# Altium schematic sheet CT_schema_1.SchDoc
size 568 x 258 mm
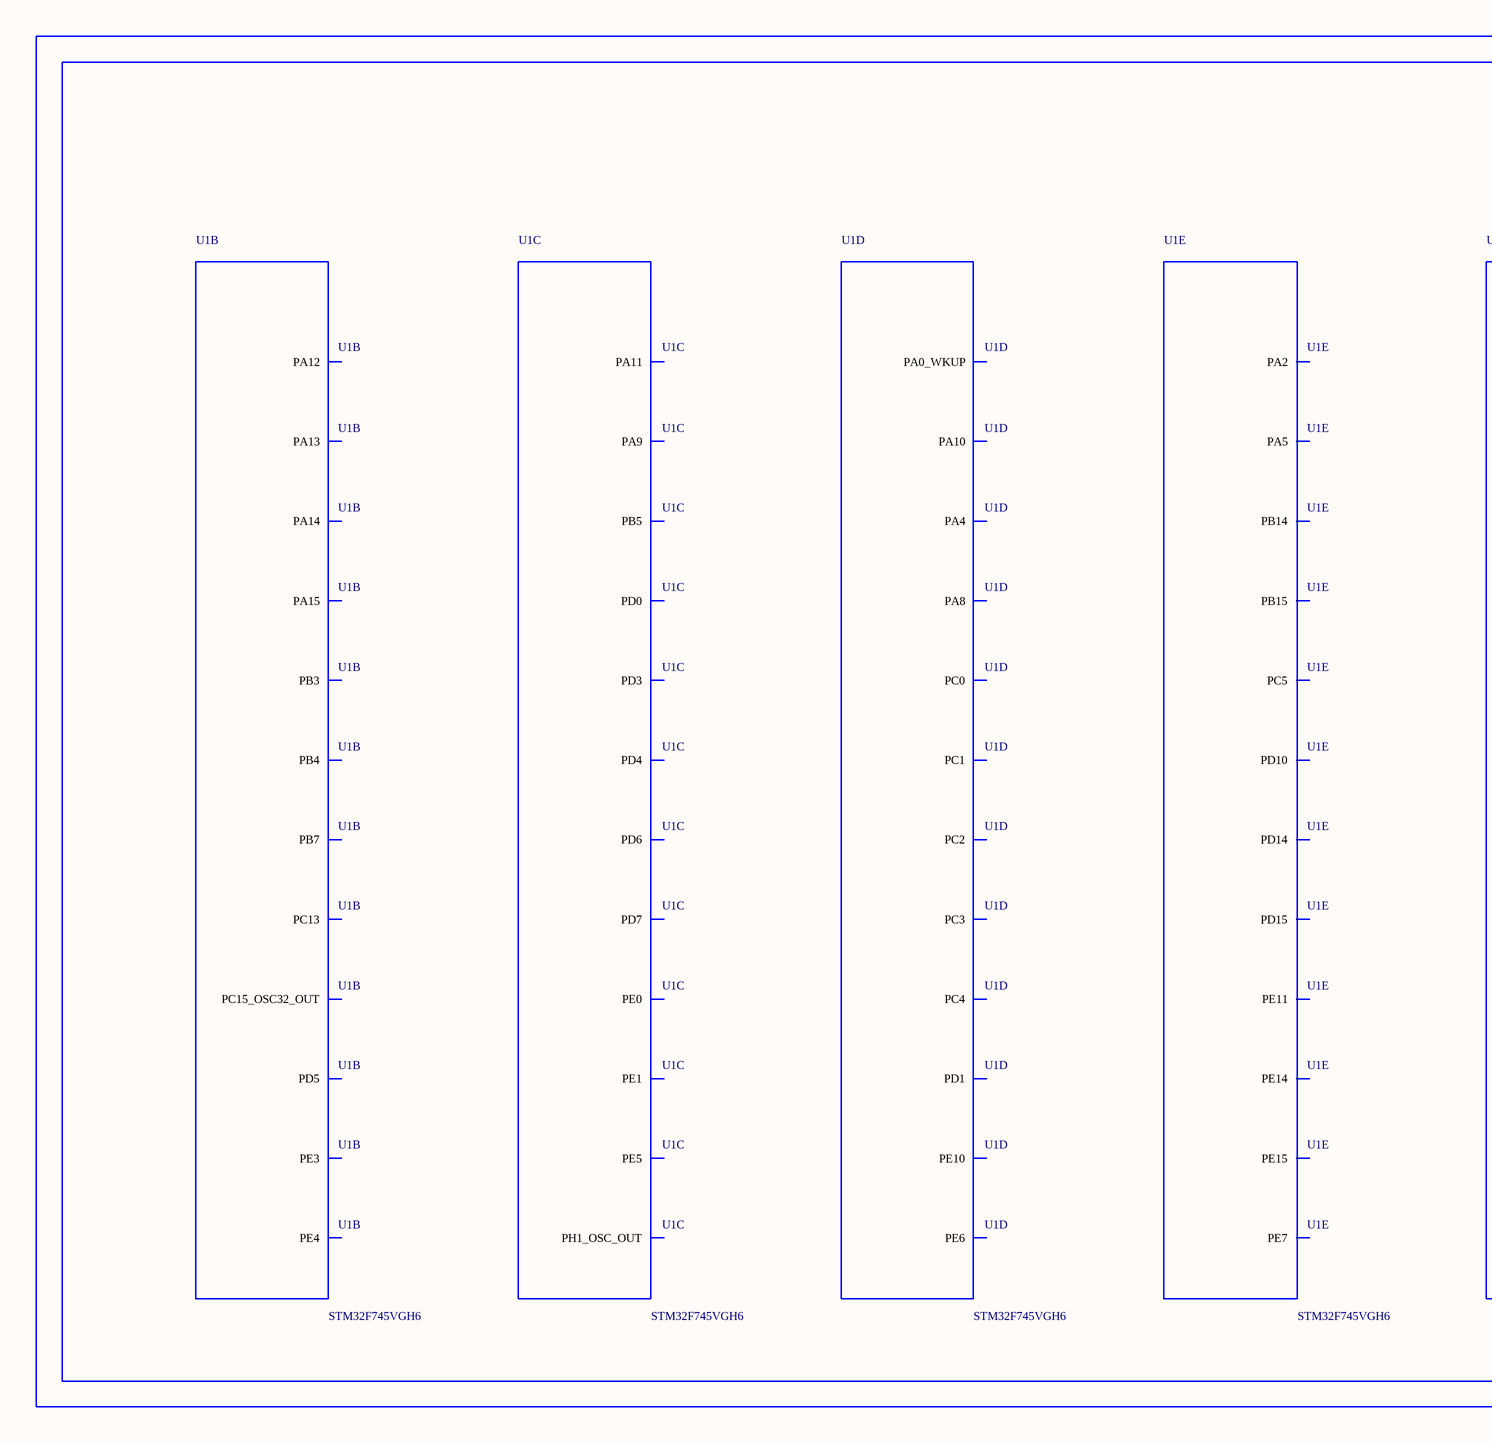
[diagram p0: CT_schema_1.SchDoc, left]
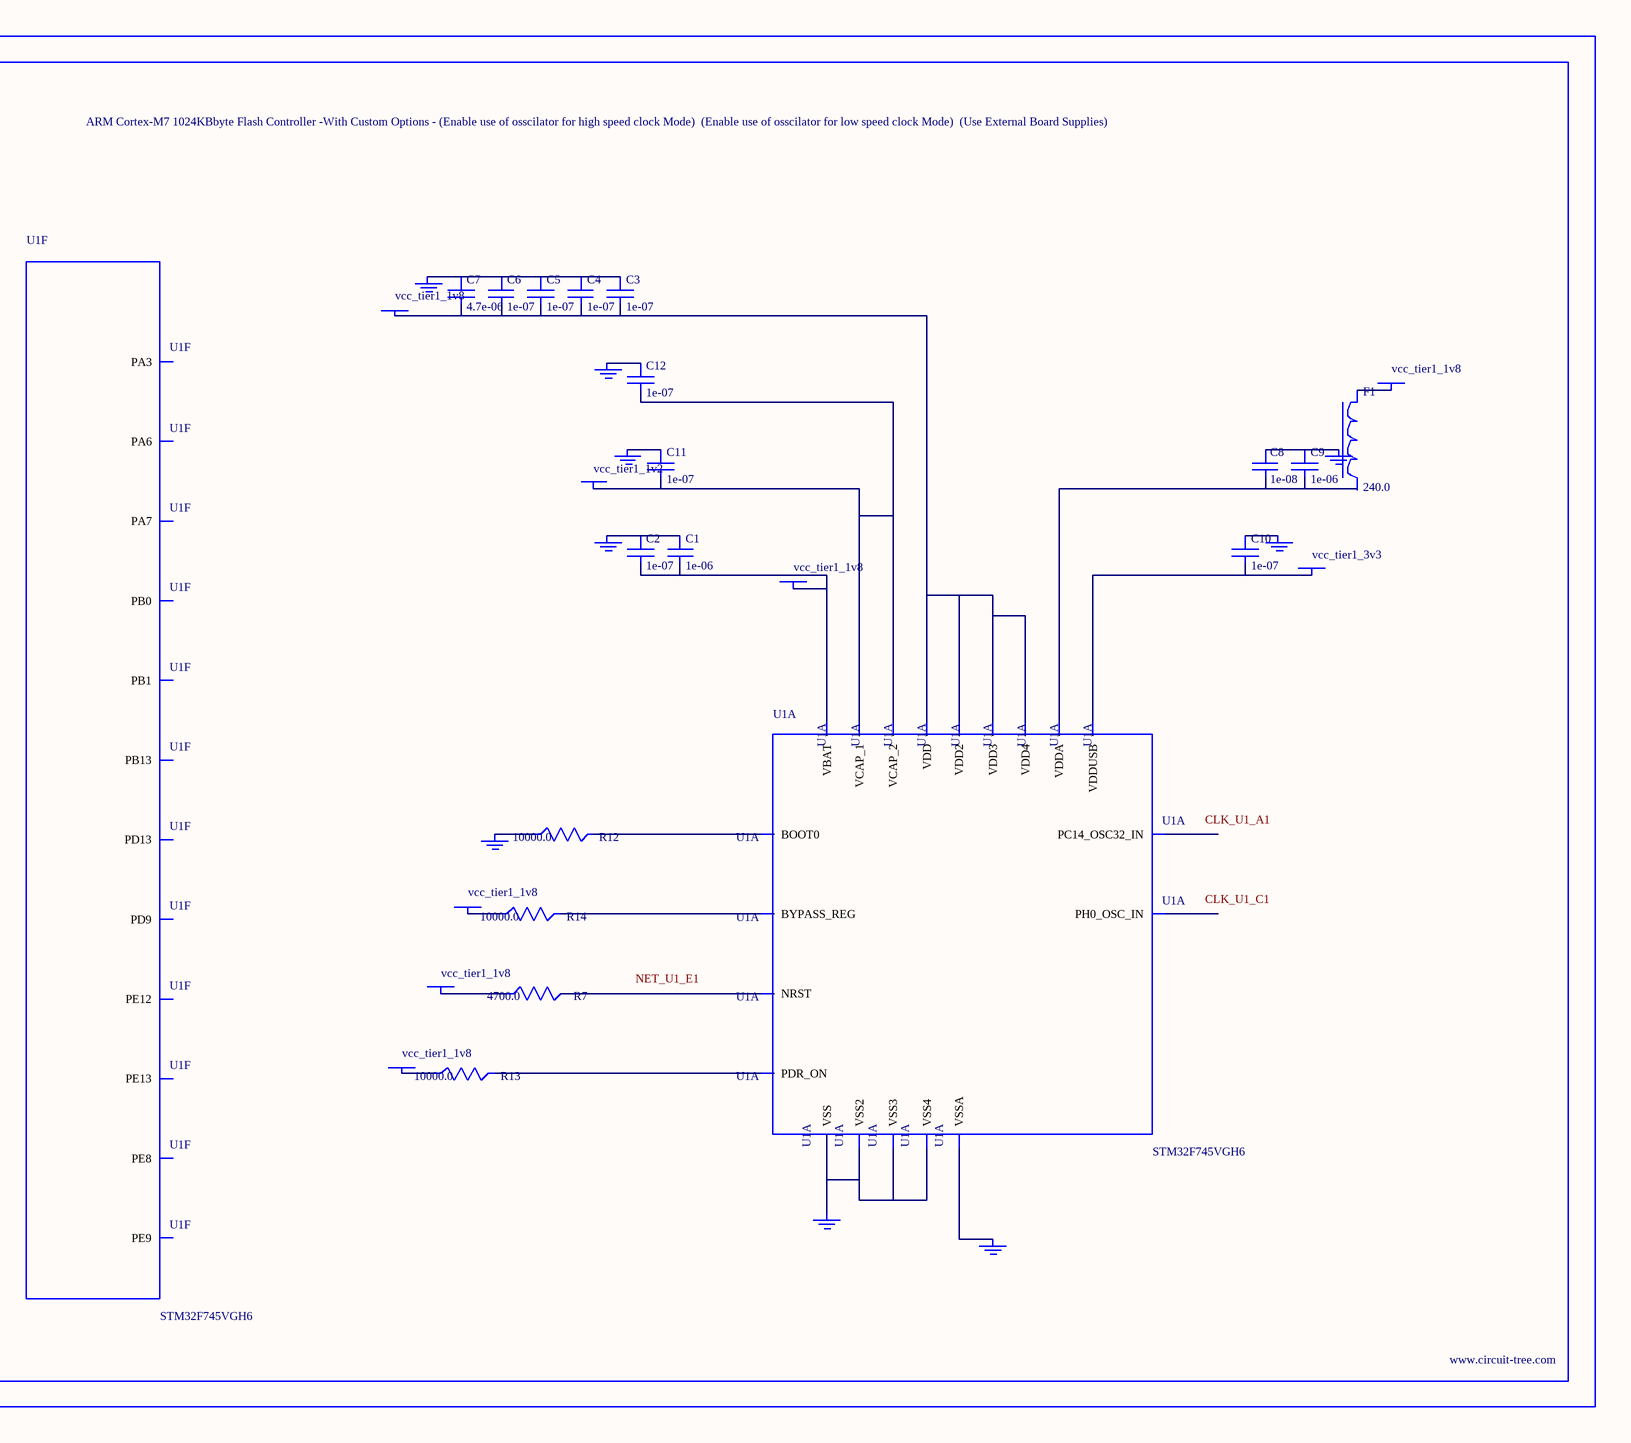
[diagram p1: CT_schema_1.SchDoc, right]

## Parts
BORDER0  (no value)
C1  1e-06  [C0603]
C2  1e-07  [C0603]
C3  1e-07  [C0603]
C4  1e-07  [C0603]
C5  1e-07  [C0603]
C6  1e-07  [C0603]
C7  4.7e-06  [C0603]
C8  1e-08  [C0603]
C9  1e-06  [C0603]
C10  1e-07  [C0603]
C11  1e-07  [C0603]
C12  1e-07  [C0603]
F1  240.0  [L0603]
GND_INSTANCE_0_0  (no value)
GND_INSTANCE_0_1  (no value)
GND_INSTANCE_0_2  (no value)
GND_INSTANCE_0_3  (no value)
GND_INSTANCE_0_4  (no value)
GND_INSTANCE_0_5  (no value)
GND_INSTANCE_0_6  (no value)
GND_INSTANCE_0_7  (no value)
GND_INSTANCE_0_8  (no value)
POWER_INSTANCE_0_0  vcc_tier1_1v8
POWER_INSTANCE_0_1  vcc_tier1_1v8
POWER_INSTANCE_0_2  vcc_tier1_1v8
POWER_INSTANCE_0_3  vcc_tier1_1v8
POWER_INSTANCE_0_4  vcc_tier1_3v3
POWER_INSTANCE_0_5  vcc_tier1_1v8
POWER_INSTANCE_0_6  vcc_tier1_1v2
POWER_INSTANCE_0_7  vcc_tier1_1v8
R7  4700.0  [R0603]
R12  10000.0  [R0603]
R13  10000.0  [R0603]
R14  10000.0  [R0603]
U1  STM32F745VGH6  [TFBGA100]  (parts A,B,C,D,E,F of 9)

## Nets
NetC1_1: C1.1 C2.1 GND_INSTANCE_0_0.0(GND)
NetC1_2: C1.2 C2.2 POWER_INSTANCE_0_0.0(PWR) U1.B2(VBAT)
NetC3_1: C3.1 C4.1 C5.1 C6.1 C7.1 GND_INSTANCE_0_2.0(GND)
NetC3_2: C3.2 C4.2 C5.2 C6.2 C7.2 POWER_INSTANCE_0_2.0(PWR) U1.D2(VDD) U1.F4(VDD2) U1.F5(VDD3) U1.K1(VDD4)
NetC8_1: C8.1 C9.1 GND_INSTANCE_0_1.0(GND)
NetC8_2: C8.2 C9.2 U1.H1(VDDA)
NetC10_1: C10.1 GND_INSTANCE_0_4.0(GND)
NetC10_2: C10.2 POWER_INSTANCE_0_4.0(PWR) U1.F6(VDDUSB)
NetC11_1: C11.1 GND_INSTANCE_0_5.0(GND)
NetC11_2: C11.2 C12.2 POWER_INSTANCE_0_6.0(PWR) U1.E7(VCAP_2) U1.F8(VCAP_1)
NetC12_1: C12.1 GND_INSTANCE_0_6.0(GND)
NetF1_1: F1.1 POWER_INSTANCE_0_1.0(PWR)
NetGND_INSTANCE_0_3_0: GND_INSTANCE_0_3.0(GND) R12.1
NetGND_INSTANCE_0_7_0: GND_INSTANCE_0_7.0(GND) U1.G1(VSSA)
NetGND_INSTANCE_0_8_0: GND_INSTANCE_0_8.0(GND) U1.C2(VSS) U1.E4(VSS2) U1.E5(VSS3) U1.J1(VSS4)
NetPOWER_INSTANCE_0_3_0: POWER_INSTANCE_0_3.0(PWR) R13.1
NetPOWER_INSTANCE_0_5_0: POWER_INSTANCE_0_5.0(PWR) R14.1
NetPOWER_INSTANCE_0_7_0: POWER_INSTANCE_0_7.0(PWR) R7.1
NetR7_2: R7.2 U1.E1(NRST)
NetR12_2: R12.2 U1.D5(BOOT0)
NetR13_2: R13.2 U1.F7(PDR_ON)
NetR14_2: R14.2 U1.E6(BYPASS_REG)

Not connected (* = marked no-connect by the designer): F1 2; U1 A1(PC14_OSC32_IN) A2(PC13) A5(PB7) A6(PB4) A7(PB3) A8(PA15) A9(PA14) A10(PA13) B1(PC15_OSC32_OUT) B3(PE3) B6(PD5) B10(PA12) C1(PH0_OSC_IN) C3(PE4) C4(PE1) C5(PB5) C6(PD6) C7(PD3) C9(PA9) C10(PA11) D1(PH1_OSC_OUT) D3(PE5) D4(PE0) D6(PD7) D7(PD4) D8(PD0) D9(PA8) D10(PA10) E2(PC2) E3(PE6) E8(PD1) F1(PC0) F2(PC1) F3(PC3) G2(PA0_WKUP) G3(PA4) G4(PC4) G6(PE10) G7(PE14) G8(PD15) G10(PB15) H3(PA5) H4(PC5) H5(PE7) H6(PE11) H7(PE15) H8(PD14) H9(PD10) H10(PB14) J2(PA2) J3(PA6) J4(PB0) J5(PE8) J6(PE12) J8(PB13) J9(PD9) J10(PD13) K2(PA3) K3(PA7) K4(PB1) K5(PE9) K6(PE13)

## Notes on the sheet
- Labels drawn without touching a wire or pin: CLK_U1_A1, CLK_U1_C1, NET_U1_E1

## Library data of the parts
BORDER0 = BORDER_PAGE0
C1 C9 = C0603C105K3RACTU
C2-C6 C10-C12 = 06035C104K4Z2A
C7 = GRM188R6YA475KE15D
C8 = 06035C103K4Z2A
F1 = Z0603C241ASMST
GND_INSTANCE_0_0-GND_INSTANCE_0_8 = GND
POWER_INSTANCE_0_0-POWER_INSTANCE_0_7 = PWR
R7 = RC0603JR-074K7L
R12-R14 = RC0603JR-0710KL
